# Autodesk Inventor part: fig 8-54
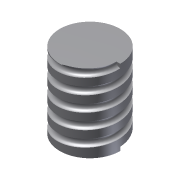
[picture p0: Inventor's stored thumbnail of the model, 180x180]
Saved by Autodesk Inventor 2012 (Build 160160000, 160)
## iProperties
Shininess: 77.0
Length Units: 11269
Angle Units: 11279
Time Units: 11290
Mass Units: 11283
Length Display Precision: 3
Angle Display Precision: 2
Created: 2002-01
Part Number: fig 8-54
Document SubType Name: Modeling
Designer: CADSoft
Density: 1 g/cm^3
Material: Default
Density: 0.0
Volumn: 0.0
Area: 0.0
PropertySet Name: Model Information
Control State: 0
Master: False
Checked Out: False
Author: CADSoft
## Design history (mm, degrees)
sketch "Sketch4"
  geometry: C1 r 20 at (0, 0)
  constraints: 1 centre point
  dimensions: "d44" = 40 diameter of C1
sketch "Sketch2"
  geometry: C1 r 2.5 at (-20, -0.092); 1 further point
  constraints: 1 centre point, 1 other
  dimensions: "d0" = 5 diameter of C1; "d43" = 20 horizontal distance of C1.centre point (0, 0)
extrude "Extrusion2" join sketch "Sketch4" distance "d45" = 50; taper "d46" = 0 deg
coil "Coil6" pitch "d47" = 10; turns "d49" = 5; dims "d48" = 10, "d50" = 0, angle "d51" = 90 deg, angle "d52" = 90 deg, "d53" = 0, "d54" = 0
body "Solid1"
